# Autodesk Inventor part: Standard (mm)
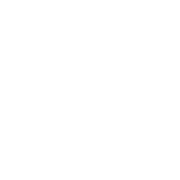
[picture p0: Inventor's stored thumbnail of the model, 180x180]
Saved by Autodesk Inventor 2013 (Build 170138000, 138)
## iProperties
Part Number: Standard (mm)
Document SubType Name: Modeling
Density: 1 g/cm^3
Material: Allgemein
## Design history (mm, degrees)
node "Volumenkörpern"
node "Oberflächenkörpern"
